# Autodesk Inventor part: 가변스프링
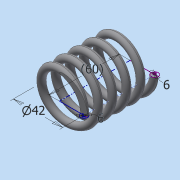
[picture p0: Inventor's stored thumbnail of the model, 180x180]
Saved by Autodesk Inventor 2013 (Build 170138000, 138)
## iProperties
Created: 2019-10
Part Number: 가변스프링
Material: 일반
Document SubType Name: Modeling
Designer: dgall
Density: 1 g/cm^3
Author: dgall
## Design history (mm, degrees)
sketch "스케치1"
  geometry: L1 (0, 0)-(21, 0); L2 (21, 0)-(21, 60); L3 (21, 60)-(0, 60); L4 (0, 60)-(0, 0); L5 (21.948, 60)-(23.481, 60); L6 (21.948, 0)-(23.481, 0); C1 r 3 at (21, 60); C2 r 3 at (21, 0)
  constraints: 12 end point, 3 parallel, 2 centre point, 2 coincident, 2 perpendicular, 1 horizontal
  dimensions: "d0" = 60 distance of L3.end L1.start (derived); "d1" = 42 diameter of L2 L4; "d2" = 6 diameter of C1; "d3" = 6 diameter of C2
feature "코일1" pitch "d4" = 10; turns "d6" = 5; dims "d5" = 60, "d7" = 0, angle "d8" = 90 deg, angle "d9" = 90 deg, "d10" = 0, "d11" = 0
feature "분할1"
feature "분할2"
node "솔리드1"
